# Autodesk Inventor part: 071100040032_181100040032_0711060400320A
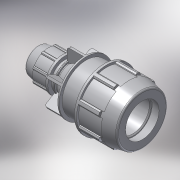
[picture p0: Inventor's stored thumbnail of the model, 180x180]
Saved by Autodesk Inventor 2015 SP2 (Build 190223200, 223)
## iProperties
Created: 2017-02
Part Number: 071100040032_181100040032_0711060400320A
Material: PVC-Piping
Description: PLASSON REDUCING COUPLER 40-32
Document SubType Name: Modeling
Designer: KIM
Mass: 92.6774 g
Surface Area: 199.44 cm^2
Volume: 66.1981 cm^3
Density: 1.4 g/cm^3
Appearance: Smooth - White
Author: KIM
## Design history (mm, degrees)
derived "07110.ipt"
feature "Solid1::07110.ipt"
tag "TaggingFeature1"
body "Solid1"
other parameters: "d4" = 13, "d5" = 22.28571, "d7" = 82, "d9" = 22.28571, "d11" = 2.22857, "d12" = 65.6, "d13" = 120 deg, "d15" = 12 deg, "d16" = 73.8, "d18" = 2, "d19" = 35 deg, "d20" = 17.5 deg, "d21" = 76.26, "d23" = 0, "d25" = 360 deg, "d27" = 1.64, "d42" = 34.32, "d46" = 1.2, "d51" = 156, "d52" = 22.28571, "d53" = 12 deg, "d54" = 84, "d56" = 48, "d57" = 32, "d58" = 36, "d59" = 28.8, "d60" = 57.6, "d61" = 51.2, "d62" = 15.6, "d63" = 24.96, "d64" = 120 deg, "d65" = 64, "d68" = 11.14286, "d74" = 59.52, "d75" = 35 deg, "d76" = 17.5 deg, "d78" = 0, "d80" = 360 deg, "d85" = 1.28, "d88" = 0.64, "d93" = 67, "d94" = 57.4, "d97" = 3.03333, "d98" = 4.26667, "d99" = 0, "d100" = 3.28, "d102" = 360 deg, "d104" = 2, "d106" = 0, "d107" = 4.26667, "d108" = 0, "d109" = 4.26667, "d110" = 0, "E_" = 82, "H_" = 156, "l_" = 84, "d_1" = 32, "E_1" = 64, "l_1" = 67, "d96" = 9.1
